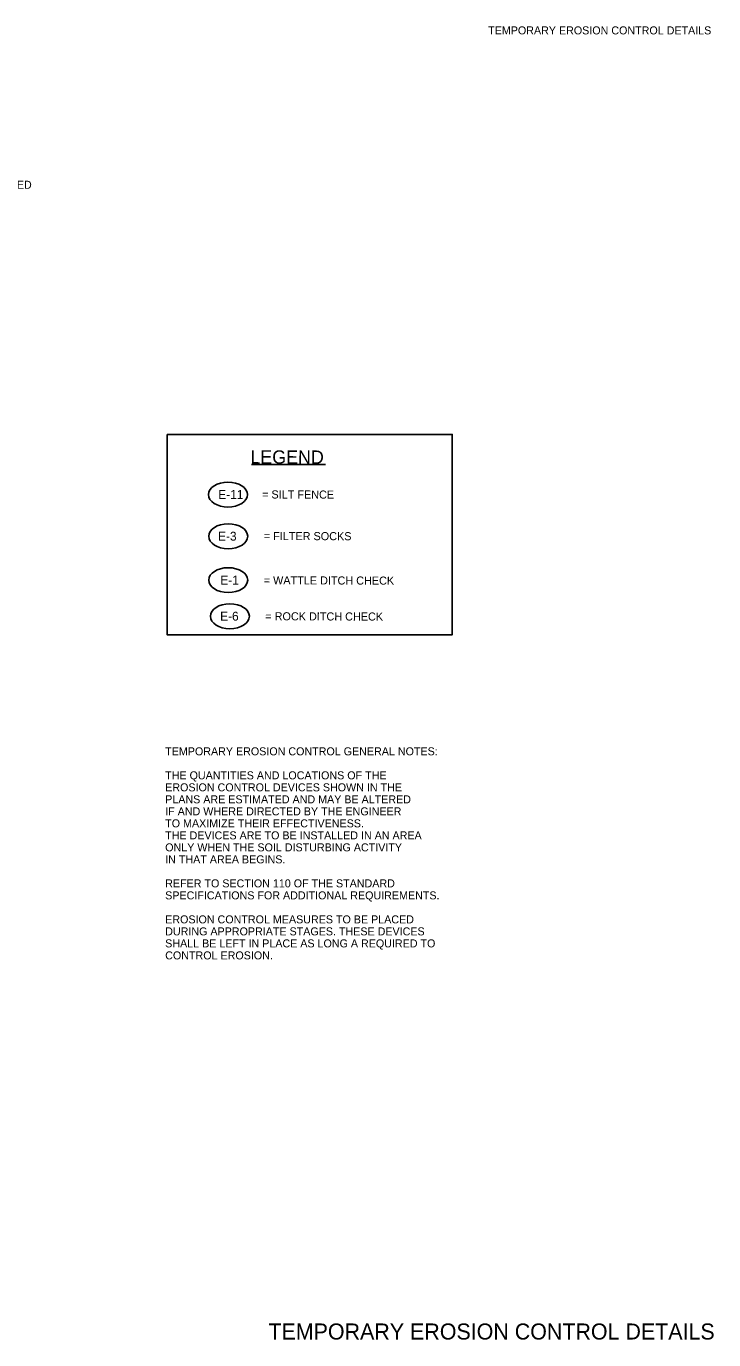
# Model space of a CAD drawing. Extents: x 1929624 to 1932072, y 596315 to 605533.
# Drawn here: x 1931557 to 1932072, y 604548 to 605533 of the extents above; entities that cross this region are included whole.
import ezdxf

# ---------------------------------------------------------------- set-up
doc = ezdxf.new("R2010")
doc.units = 0
for name, color, linetype in [('Default', 7, 'Continuous'), ('R_Border', 7, 'Continuous'), ('R_Border Prem', 7, 'Continuous')]:
    doc.layers.add(name, color=color, linetype=linetype)

msp = doc.modelspace()

# ---------------------------------------------------------------- linework, layer by layer
at = {"layer": 'R_Border'}
msp.add_line((1931725.56, 605204.24), (1931781.07, 605204.24), dxfattribs=at)
msp.add_lwpolyline([(1931662.33, 605226.81), (1931875.97, 605226.81), (1931875.97, 605076.56), (1931662.33, 605076.56)], close=True, dxfattribs=at)
for centre in [(1931707.88, 605181.67), (1931708.1, 605150.41), (1931708.1, 605117.51), (1931709.32, 605090.41)]:
    msp.add_ellipse(centre, major_axis=(14.6, 0), ratio=0.638788, dxfattribs=at)

# ---------------------------------------------------------------- texts
at = {"layer": 'Default'}
msp.add_text('IF AND WHERE DIRECTED', height=6, dxfattribs=at).set_placement((1931459.23, 605410.92))
for s, height, p in [('LEGEND', 10, (1931724.71, 605204.87)), ('= SILT FENCE', 6.075, (1931733.48, 605178.75)), ('= FILTER SOCKS', 6.075, (1931734.76, 605147.6)), ('= WATTLE DITCH CHECK', 6.075, (1931734.7, 605114.38)), ('= ROCK DITCH CHECK', 6.075, (1931735.87, 605087.41))]:
    msp.add_text(s, height=height, rotation=359.82713, dxfattribs=at).set_placement(p)
at = {"layer": 'R_Border'}
for s, p in [('E-11', (1931700.66, 605178.4)), ('E-3', (1931700.49, 605147.13)), ('E-1', (1931702.2, 605114.23)), ('E-6', (1931702.05, 605087.13))]:
    msp.add_text(s, height=6.663, rotation=360, dxfattribs=at).set_placement(p)
for s, height, p in [('TEMPORARY EROSION CONTROL GENERAL NOTES:', 6, (1931660.88, 604986.16)), ('THE QUANTITIES AND LOCATIONS OF THE', 6, (1931660.88, 604968.16)), ('EROSION CONTROL DEVICES SHOWN IN THE ', 6, (1931660.88, 604959.16)), ('PLANS ARE ESTIMATED AND MAY BE ALTERED ', 6, (1931660.88, 604950.16)), ('IF AND WHERE DIRECTED BY THE ENGINEER ', 6, (1931660.88, 604941.16)), ('TO MAXIMIZE THEIR EFFECTIVENESS. ', 6, (1931660.88, 604932.16)), ('THE DEVICES ARE TO BE INSTALLED IN AN AREA ', 6, (1931660.88, 604923.16)), ('ONLY WHEN THE SOIL DISTURBING ACTIVITY', 6, (1931660.88, 604914.16)), ('IN THAT AREA BEGINS.', 6, (1931660.88, 604905.16)), ('REFER TO SECTION 110 OF THE STANDARD ', 6, (1931660.88, 604887.16)), ('SPECIFICATIONS FOR ADDITIONAL REQUIREMENTS.', 6, (1931660.88, 604878.16)), ('EROSION CONTROL MEASURES TO BE PLACED', 6, (1931660.88, 604860.16)), ('DURING APPROPRIATE STAGES. THESE DEVICES', 6, (1931660.88, 604851.16)), ('SHALL BE LEFT IN PLACE AS LONG A REQUIRED TO ', 6, (1931660.88, 604842.16)), ('CONTROL EROSION.', 6, (1931660.88, 604833.16)), ('TEMPORARY EROSION CONTROL DETAILS', 12, (1931738.22, 604548.18))]:
    msp.add_text(s, height=height, dxfattribs=at).set_placement(p)
at = {"layer": 'R_Border Prem'}
msp.add_text('TEMPORARY EROSION CONTROL DETAILS ', height=6, rotation=359.99339, dxfattribs=at).set_placement((1931902.85, 605526.69))

doc.saveas('drawing.dxf')
